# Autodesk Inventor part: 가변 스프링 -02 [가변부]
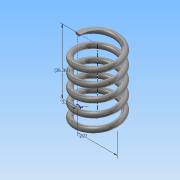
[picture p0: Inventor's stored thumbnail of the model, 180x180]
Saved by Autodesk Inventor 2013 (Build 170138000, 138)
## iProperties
Created: 2014-12
Part Number: 가변 스프링 -02 [가변부]
Material: 강철, 탄소
Document SubType Name: Modeling
Designer: Administrator
Density: 7.87 g/cm^3
Mass: 18.8875 g
Surface Area: 32.5169 cm^2
Volume: 2.39994 cm^3
Author: Administrator
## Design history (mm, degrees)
sketch "Sketch1"
  geometry: L1 (0, 0)-(11, 0); L2 (11, 0)-(11, 36.261); L3 (11, 36.261)-(0, 36.261); L4 (0, 36.261)-(0, 0); C1 r 1.5 at (11, 0)
  constraints: 8 end point, 2 parallel, 1 centre point, 1 coincident, 1 horizontal, 1 perpendicular
  dimensions: "d0" = 3 diameter of C1; "d1" = 22 diameter of L2 L4; "d2" = 36.2612 distance between parallel lines of L1 L3 (derived)
coil "Coil1" pitch "d3" = 10; turns "d5" = 5; dims "d4" = 36.2612 (= d2), "d6" = 0, angle "d7" = 90 deg, angle "d8" = 90 deg, "d9" = 0, "d10" = 0
sketch "Sketch2"
  geometry: L1 (-12.5, 0)-(-9.5, 0) reference; 1 further point
  constraints: 1 horizontal alignment
extrude "Extrusion1" cut sketch "Sketch2" stored distance "d11" = 10; taper "d12" = 0 deg
workplane "Work Plane2"
sketch "Sketch3"
  geometry: L1 (1.5, 0)-(-1.5, 0) reference; 1 further point
  constraints: 1 horizontal alignment
extrude "Extrusion2" cut sketch "Sketch3" stored distance "d14" = 10; taper "d15" = 0 deg
body "Solid1"
node "Project Cut Edges1"
node "Project Cut Edges2"
other parameters: "d13" = 0
